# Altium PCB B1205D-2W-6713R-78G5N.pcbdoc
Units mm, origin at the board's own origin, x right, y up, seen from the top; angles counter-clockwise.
Board outline 40 x 23 mm, 2 copper layers (Top Layer, Bottom Layer), stack 0.78 mm thick; 19 components, 10 nets, 42 pads, 26 vias.
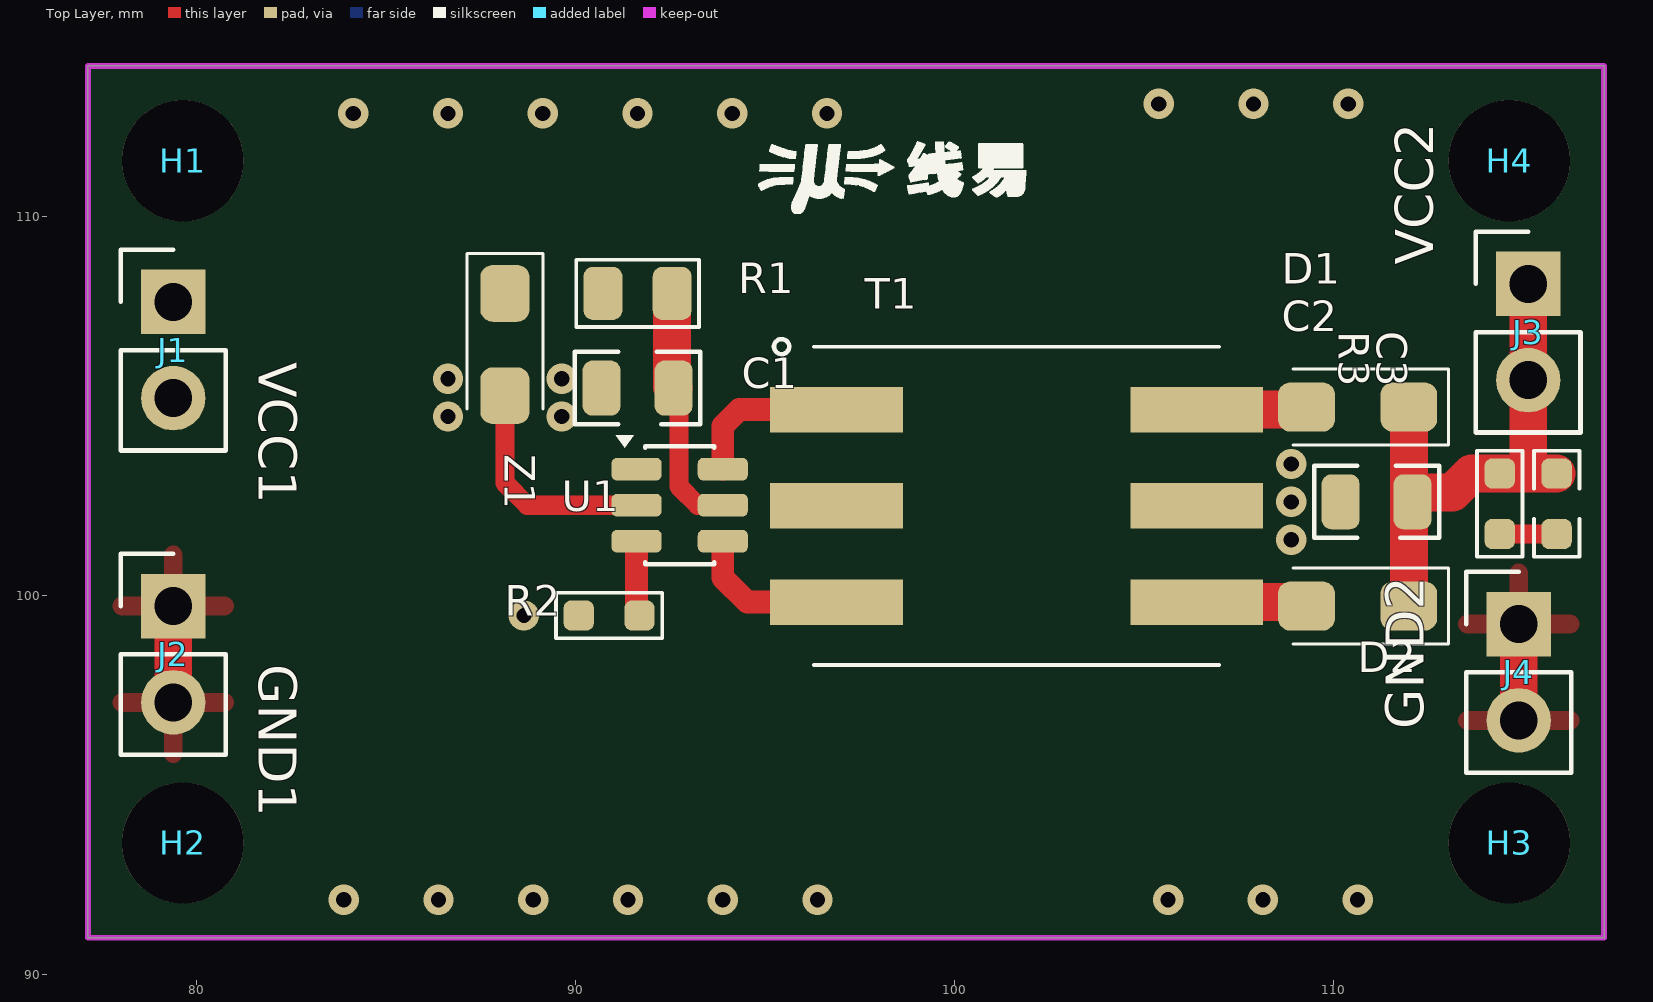
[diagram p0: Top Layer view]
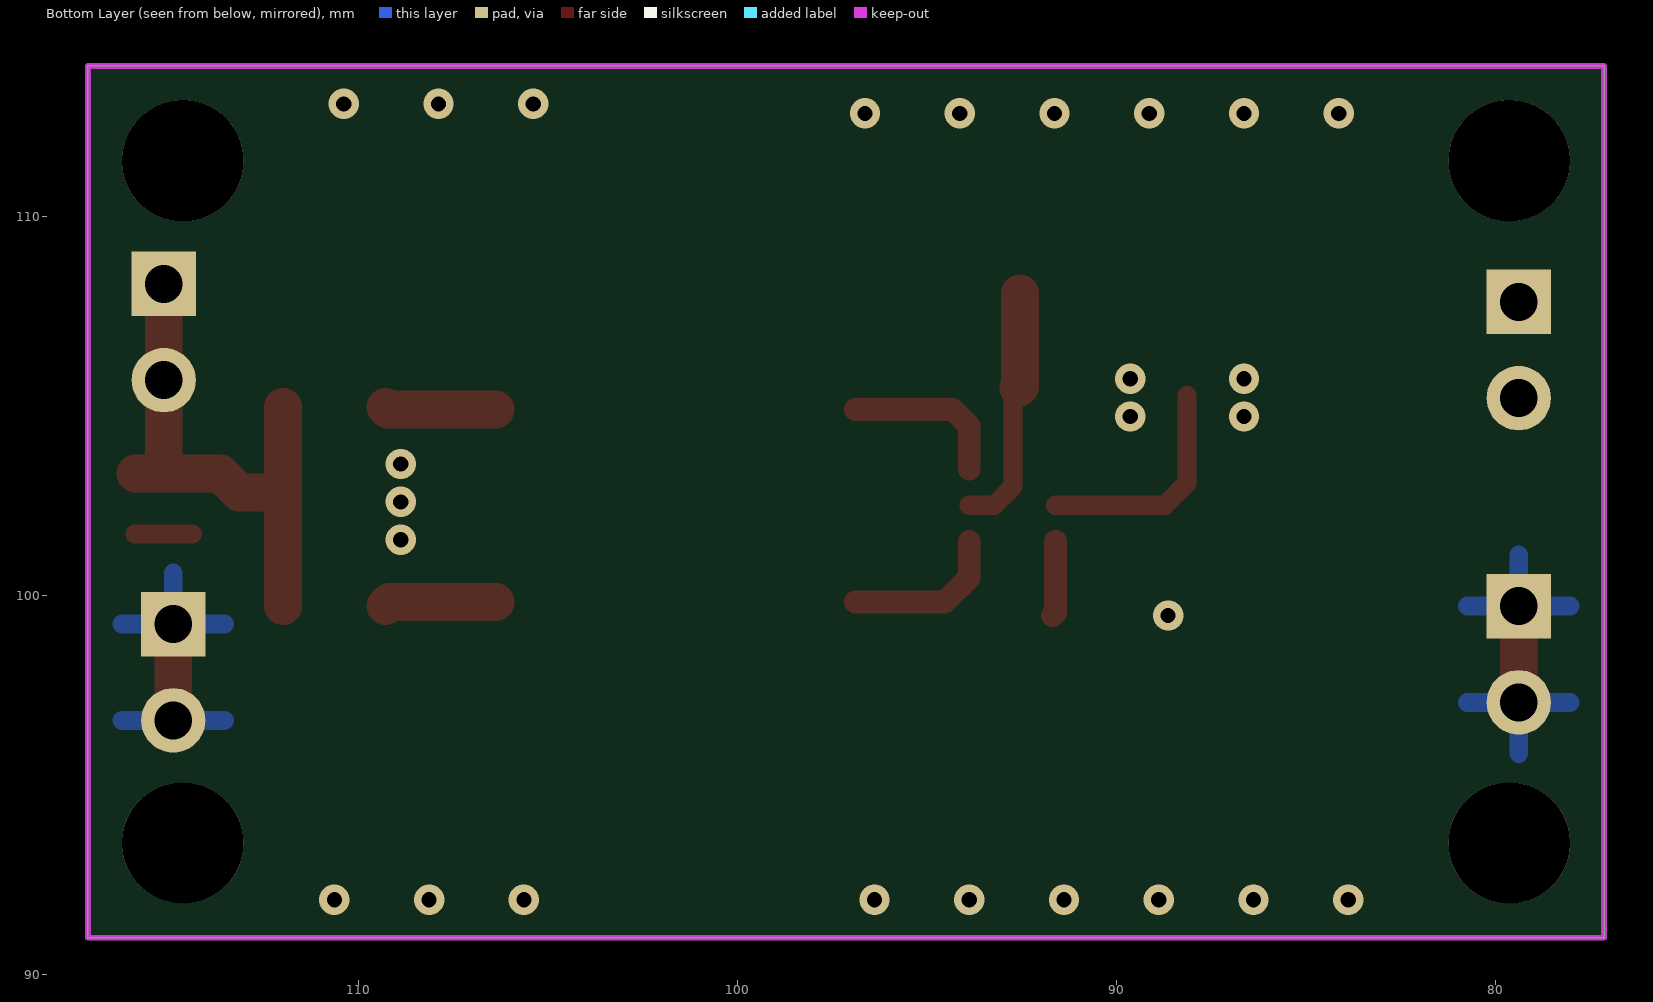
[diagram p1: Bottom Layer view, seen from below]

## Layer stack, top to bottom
Top Solder Mask Layer: solder mask 0.01, Dk 0
Top Layer: signal copper 0.035
dielectric 1: surface 0.71, FR4, Dk 4.5
Bottom Layer: signal copper 0.035
Bottom Solder Mask Layer: solder mask 0.01, Dk 0

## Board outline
77.15,90.981 77.15,113.981 117.15,113.981 117.15,90.981

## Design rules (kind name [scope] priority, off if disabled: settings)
BoardOutlineClearance copperThickness1oz [All] p0: genericclearance=0.254 ignorepadtopadclearanceinfootprint=FALSE except(0: Arc-SplitContinuation Track-SplitContinuation SMDPad-SplitContinuation THPad-SplitContinuation Via-SplitContinuation Fill-SplitContinuation Poly-SplitContinuation Region-SplitContinuation Text-SplitContinuation)
BoardOutlineClearance otherClearance [All] p0: genericclearance=0.254 ignorepadtopadclearanceinfootprint=FALSE except(0: Arc-SplitContinuation Track-SplitContinuation SMDPad-SplitContinuation THPad-SplitContinuation Via-SplitContinuation Fill-SplitContinuation Poly-SplitContinuation Region-SplitContinuation Text-SplitContinuation)
Clearance copperThickness1oz [All] p1: gap=0.178 ignorepadtopadclearanceinfootprint=FALSE
Clearance otherClearance [All] p1: gap=0.178 ignorepadtopadclearanceinfootprint=FALSE
DiffPairsRouting differentialPair [All] p1: maxuncoupledlength=10 minlimit=5 maxlimit=Infinity mostfreqgap=6 toplayer_minwidth=5 toplayer_prefwidth=100 toplayer_maxwidth=100 bottomlayer_minwidth=5 bottomlayer_prefwidth=100 bottomlayer_maxwidth=100
PasteMaskExpansion pasteMaskExpansion [All] p1: expansion=0
PlaneConnect innerPlane [All] p1: planeconnectstyle=Relief reliefexpansion=0.508 reliefentries=4 reliefconductorwidth=0.254 reliefairgap=0.254
PolygonConnect copper0 [All] p1: connectstyle=Direct reliefentries=4 reliefconductorwidth=10 polygonreliefangle="90 Angle" airgapwidth=10
PolygonConnect copper1 [All] p1: connectstyle=Relief reliefentries=4 reliefconductorwidth=19.685 polygonreliefangle="90 Angle" airgapwidth=19.685
RoutingVias viaSize [All] p1: viastyle="Through Hole" holewidth=24 minholewidth=11.811 maxholewidth=393.7 width=24 minwidth=11.811 maxwidth=393.7
SolderMaskExpansion solderMaskExpansion [All] p1: useseparateexpansions=TRUE expansion=2 expansionbottom=2
Width copperThickness1oz [All] p1: maxlimit=100 minlimit=5 preferedwidth=10

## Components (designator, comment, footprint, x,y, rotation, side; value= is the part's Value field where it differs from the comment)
C1 "10uF" C0805 91.65,105.481 r0 top
C2 "10uF" C0805 111.15,102.481 r0 top
C3 "100nF" C0603 115.9,102.431 r90 top
D1 "DSK24" SOD-123_L2.8-W1.8-LS3.7-RD 110.65,104.981 r180 top
D2 "DSK24" SOD-123_L2.8-W1.8-LS3.7-RD 110.65,99.731 r180 top
H1 "Mechanical_MountingHole" MountingHole:MountingHole_3.2mm_M3 79.65,111.481 r0 top
H2 "Mechanical_MountingHole" MountingHole:MountingHole_3.2mm_M3 79.65,93.481 r0 top
H3 "Mechanical_MountingHole" MountingHole:MountingHole_3.2mm_M3 114.65,93.481 r0 top
H4 "Mechanical_MountingHole" MountingHole:MountingHole_3.2mm_M3 114.65,111.481 r0 top
J1 "HX PZ2.54-1x2P ZZ" HDR-TH_2P-P2.54-V-M-3 79.4,107.756 r0 top
J2 "HX PZ2.54-1x2P ZZ" HDR-TH_2P-P2.54-V-M-3 79.4,99.731 r0 top
J3 "HX PZ2.54-1x2P ZZ" HDR-TH_2P-P2.54-V-M-3 115.15,108.231 r0 top
J4 "HX PZ2.54-1x2P ZZ" HDR-TH_2P-P2.54-V-M-3 114.9,99.256 r0 top
R1 "0Ω" R0805 91.65,107.981 r0 top
R2 "My_Library_R" MYLibrary:R0603 90.9,99.481 r0 top
R3 "2.2kΩ" R0603 114.4,102.431 r270 top
T1 "CMT78G5N" SMD-6_L9.7-W8.9-P2.54-LS12.8-TL 101.65,102.376 r0 top
U1 "CMP6713R" SOT-23-6_L2.9-W1.6-P0.95-LS2.8-BL 92.762,102.394 r0 top
Z1 "Diode_SMAJ30CA" MYLibrary:SOD-123-323 88.15,106.631 r270 top

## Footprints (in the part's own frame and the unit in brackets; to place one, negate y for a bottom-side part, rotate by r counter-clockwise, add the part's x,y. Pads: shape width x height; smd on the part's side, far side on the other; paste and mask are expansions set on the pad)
C0603 [mm]
  rrect50% 0.8x0.8 smd: 1(-0.8,0) 2(0.8,0)
  silkscreen extent -1.4,-0.6 1.4,0.6
C0805 [mm]
  rrect50% 1x1.45 smd: 1(-0.95,0) 2(0.95,0)
  silkscreen extent -1.65,-0.95 1.65,0.96
HDR-TH_2P-P2.54-V-M-3 [mm]
  rect 1.7x1.7 hole 1: 1(0,0)
  round 1.7 hole 1: 2(0,-2.54)
  silkscreen extent -1.38,-3.92 1.38,1.38
MountingHole:MountingHole_3.2mm_M3 [mm]
  round 3.2 hole 3.2 unplated: ""(0,0)
MYLibrary:R0603 [mm]
  rrect50% 0.8x0.8 smd: 1(-0.8,0) 2(0.8,0)
  silkscreen extent -1.4,-0.6 1.4,0.6
MYLibrary:SOD-123-323 [mm]
  rrect50% 1.5x1.3 smd: 1(-1.35,0) 2(1.35,0)
  silkscreen extent -2.4,-1 1.7,1
R0603 [mm]
  rrect50% 0.8x0.8 smd: 1(-0.8,0) 2(0.8,0)
  silkscreen extent -1.4,-0.6 1.4,0.6
R0805 [mm]
  rrect48% 1.025x1.4 smd: 1(-0.913,0) 2(0.913,0)
  silkscreen extent -1.62,-0.89 1.62,0.89
SMD-6_L9.7-W8.9-P2.54-LS12.8-TL [mm]
  rect 3.5x1.2 smd: 1(-4.75,2.54) 2(-4.75,0) 3(-4.75,-2.54) 4(4.75,-2.54) 5(4.75,0) 6(4.75,2.54)
  silkscreen extent -6.4,-4.2 5.35,4.4
SOD-123_L2.8-W1.8-LS3.7-RD [mm]
  rrect50% 1.5x1.3 smd: 1(-1.35,0) 2(1.35,0)
  silkscreen extent -2.4,-1 1.7,1
SOT-23-6_L2.9-W1.6-P0.95-LS2.8-BL [mm]
  rrect50% 1.325x0.6 smd: 1(-1.138,0.95) 2(-1.138,0) 3(-1.138,-0.95) 4(1.137,-0.95) 5(1.137,0) 6(1.137,0.95)
  silkscreen extent -1.69,-1.56 0.91,1.84

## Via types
v1: diameter 0.8, hole 0.4, Top Layer to Bottom Layer, 26 vias

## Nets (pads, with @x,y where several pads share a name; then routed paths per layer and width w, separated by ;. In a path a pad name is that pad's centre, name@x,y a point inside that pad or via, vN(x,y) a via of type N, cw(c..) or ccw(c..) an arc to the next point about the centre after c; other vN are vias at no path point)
$1N6: C1.2 R1.2 U1.5 | length 6.3
  Top Layer w0.508: C1.2@92.742,105.338 92.742,102.889 93.237,102.394 U1.5
  Top Layer w1: R1.2 92.562,105.519 C1.2
$1N7: T1.3 U1.4 | length 4.2
  Top Layer w0.6: U1.4 93.9,100.481 94.545,99.836 T1.3
$1N8: D2.2 T1.4 | length 2.9
  Top Layer w1: T1.4 109.195,99.836 D2.2
$1N10: T1.1 U1.6 | length 4.3
  Top Layer w0.6: U1.6 93.9,104.481 94.335,104.916 T1.1
$1N12: D1.2 T1.6 | length 2.9
  Top Layer w1: T1.6 109.235,104.916 D1.2
CLK: R2.2 U1.3 | length 2
  Top Layer w0.6: U1.3 91.625,99.556 R2.2
GND1: C1.1 J2.1 J2.2 R2.1 U1.1 U1.2 Z1.2 | length 8.6
  Top Layer w0.508: Z1.2 88.15,102.981 88.737,102.394 U1.2
  Top Layer w1: J2.2 J2.1
  other v1: 83.9,91.981 86.4,91.981 88.9,91.981 91.4,91.981 93.9,91.981 96.4,91.981 88.65,99.481 86.65,104.731 89.65,104.731 86.65,105.731 89.65,105.731 84.15,112.731 86.65,112.731 89.15,112.731 91.65,112.731 94.15,112.731 96.65,112.731
GND2: C2.1 C3.1 J4.1 J4.2 R3.2 T1.5 | length 4
  Top Layer w0.508: R3.2 C3.1
  Top Layer w1: J4.2 J4.1
  other v1: 105.65,91.981 108.15,91.981 110.65,91.981 108.9,101.481 108.9,102.481 108.9,103.481 105.4,112.981 107.9,112.981 110.4,112.981
VCC1: J1.1 J1.2 R1.1 Z1.1
VCC2: C2.2 C3.2 D1.1 D2.1 J3.1 J3.2 R3.1 | length 14.5
  Top Layer w1: D2.1 D1.1 ; C2.2 112.35,102.731 113.15,102.731 113.65,103.231 R3.1 114.9,103.231 ; J3.1 J3.2 115.15,103.481 114.9,103.231 ; C3.2 114.9,103.231
pads on no net: H1. H2. H3. H4. T1.2

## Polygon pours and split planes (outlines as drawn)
VCC1 on Top Layer (solid, remove dead copper, pour order 2): 77.9,103.731 77.9,109.481 90.45,109.481 91.25,108.681 91.25,106.981 91,106.731 82.5,106.731 81.65,105.881 81.65,103.731
GND1 on Top Layer (solid, remove dead copper, pour order 4): 77.2,115.006 98.605,115.006 98.605,90.006 77.2,90.006
GND1 on Bottom Layer (solid, remove dead copper, pour order 12): 77.2,115.006 98.605,115.006 98.605,90.006 77.2,90.006
GND2 on Top Layer (solid, remove dead copper, pour order 8): 104.63,114.031 117.15,114.031 117.15,90.981 104.63,90.981
GND2 on Bottom Layer (solid, remove dead copper, pour order 16): 104.63,114.031 117.15,114.031 117.15,90.981 104.63,90.981

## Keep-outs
Board Outline Layer:
  the board outline again, w0.15

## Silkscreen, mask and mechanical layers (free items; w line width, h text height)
Top Silkscreen Layer:
  drawing of 9 lines, arcs and shapes, not listed
  text "VCC2" at 112.65,108.731 h1 r90
  text "VCC1" at 81.65,106.161 h1 r270
  text "GND1" at 81.65,98.191 h1 r270
  text "GND2" at 112.4,96.481 h1 r90
User.Eco1:
